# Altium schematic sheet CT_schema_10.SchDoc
size 146 x 119 mm
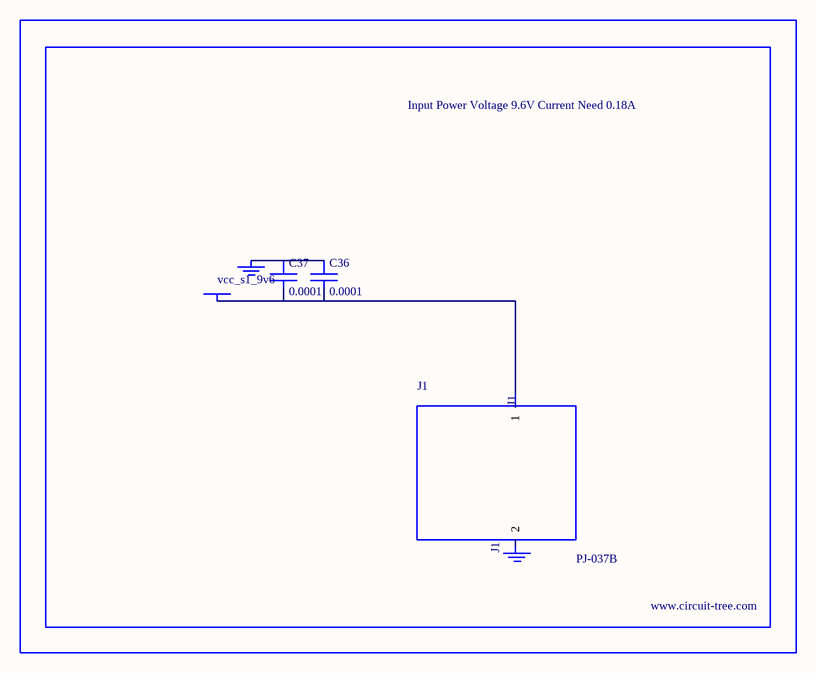
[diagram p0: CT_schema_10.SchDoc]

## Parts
BORDER9  (no value)
C36  0.0001  [EXV-9H]
C37  0.0001  [EXV-9H]
GND_INSTANCE_9_0  (no value)
GND_INSTANCE_9_1  (no value)
J1  PJ-037B  [PJ-037B_PACKAGE]
POWER_INSTANCE_9_0  vcc_s1_9v6

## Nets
NetC36_1: C36.1 C37.1 GND_INSTANCE_9_0.0(GND)
NetC36_2: C36.2 C37.2 J1.1 POWER_INSTANCE_9_0.0(PWR)

Not connected (* = marked no-connect by the designer): GND_INSTANCE_9_1 0(GND); J1 2

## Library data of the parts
BORDER9 = BORDER_PAGE9
C36 C37 = EDK107M035A9HAA
GND_INSTANCE_9_0 GND_INSTANCE_9_1 = GND
POWER_INSTANCE_9_0 = PWR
